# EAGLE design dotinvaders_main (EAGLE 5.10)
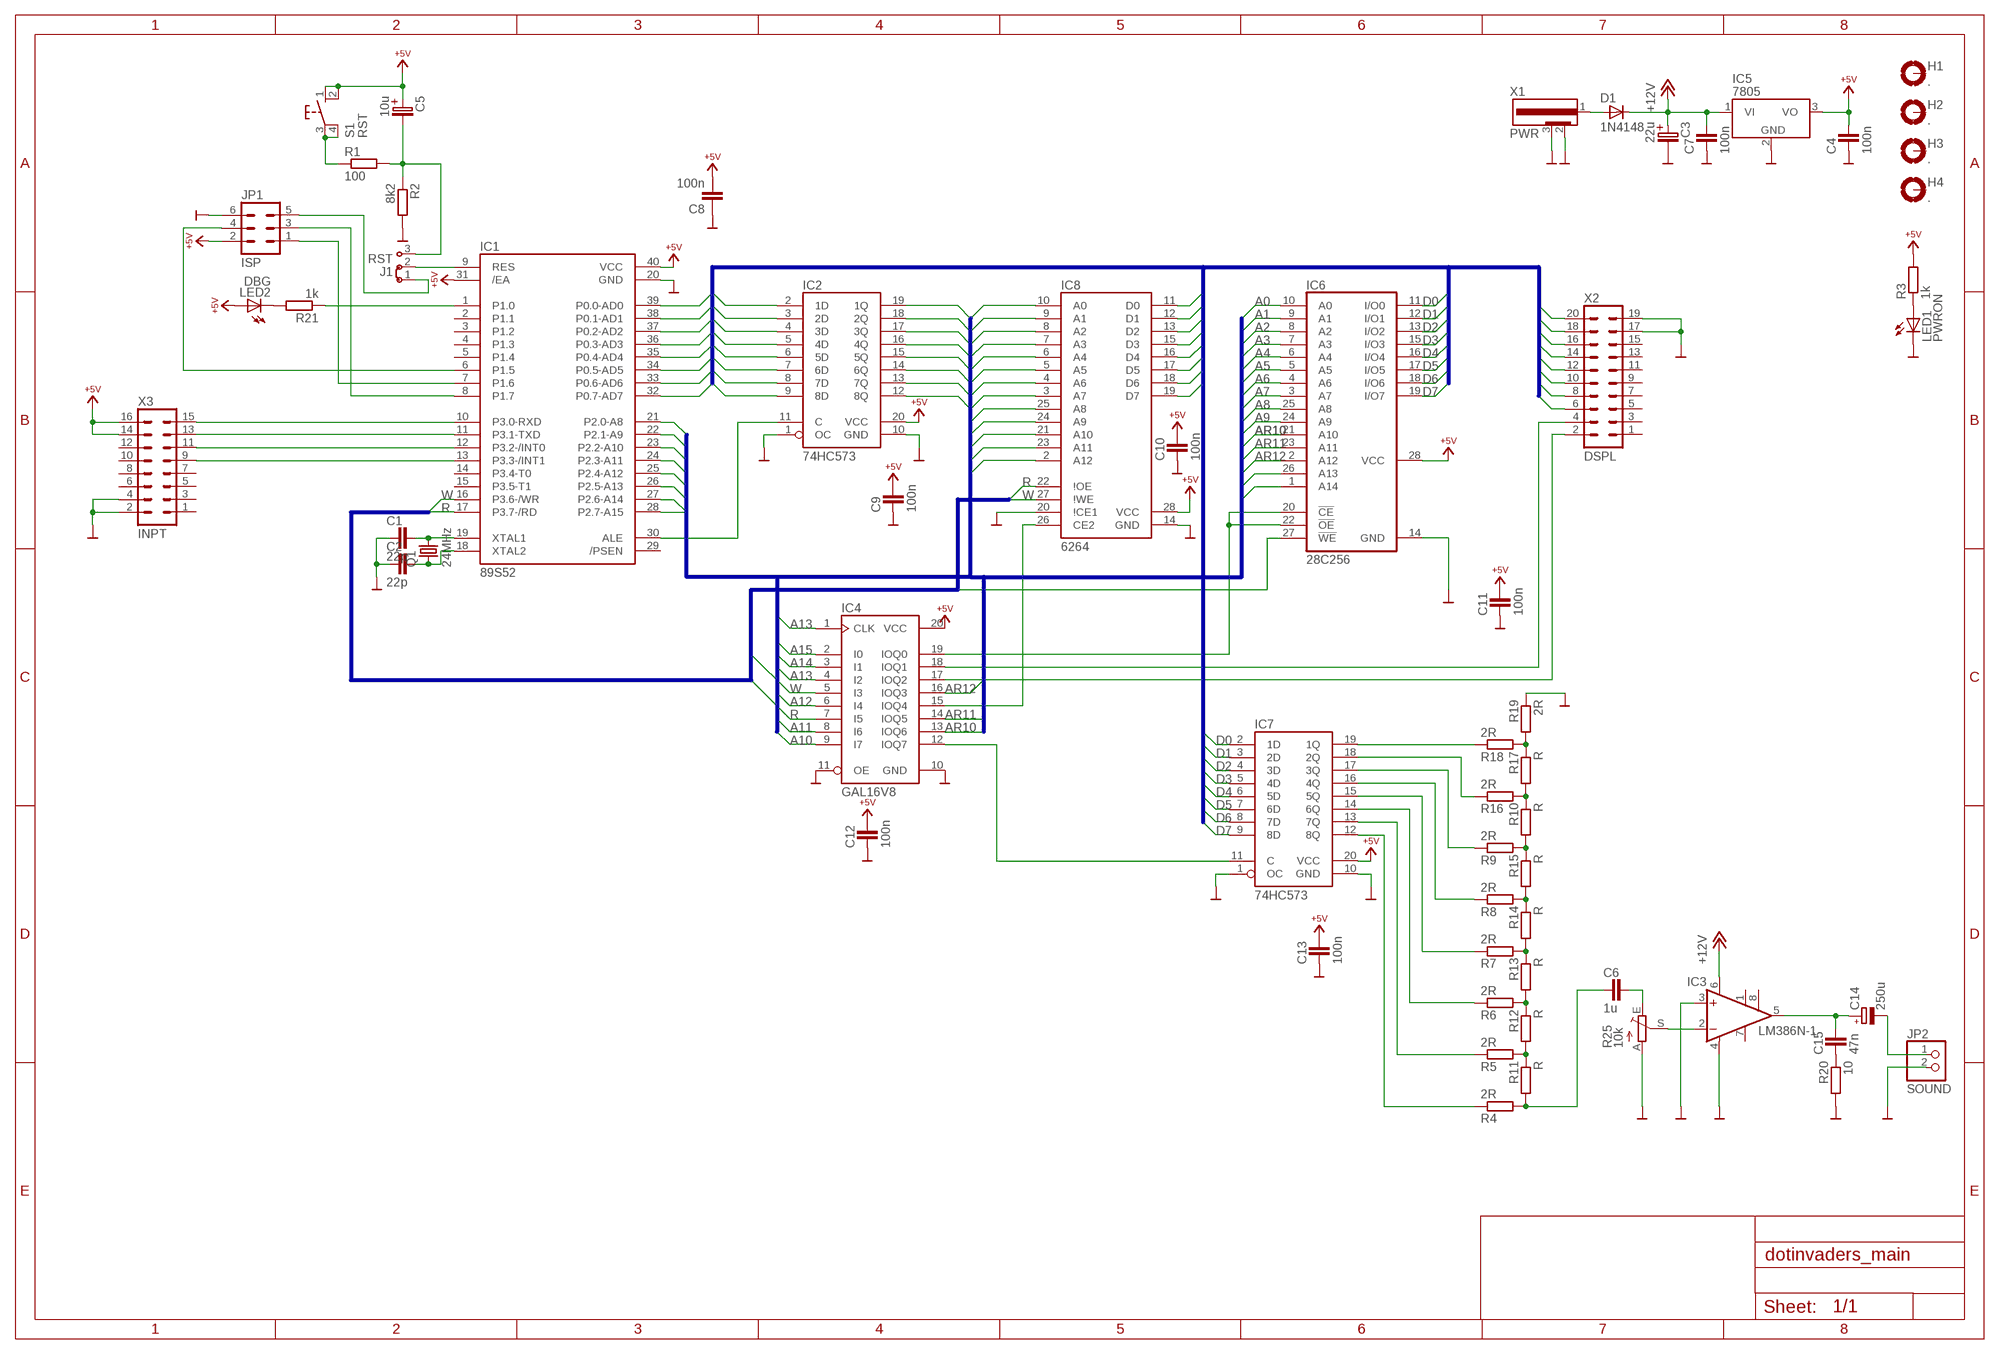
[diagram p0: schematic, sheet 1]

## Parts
C1  22p  C2,5  [C2,5]
C2  22p  C2,5  [C2,5]
C3  22u  ELKO2,5  [ELKO2,5]
C4  100n  C2,5  [C2,5]
C5  10u  ELKO2,5  [ELKO2,5]
C6  1u  C-2,5  [C-2,5]
C7  100n  C2,5  [C2,5]
C8  100n  C-EU050-024X044  [C050-024X044]
C9  100n  C-2,5  [C-2,5]
C10  100n  C-2,5  [C-2,5]
C11  100n  C-2,5  [C-2,5]
C12  100n  C-2,5  [C-2,5]
C13  100n  C-2,5  [C-2,5]
C14  250u  CPOL-EUE5-10.5  [E5-10,5]
C15  47n  C-2,5  [C-2,5]
D1  1N4148  1N4007  [DO41]
H1  .  BO3,0  [BO3,0]
H2  .  BO3,0  [BO3,0]
H3  .  BO3,0  [BO3,0]
H4  .  BO3,0  [BO3,0]
IC1  89S52  80C32  [DIL40]
IC2  74HC573  74573  [DIL20]
IC3  LM386N-1  [DIL08]
IC4  GAL16V8  16V8  [DIL20]
IC5  7805  [TO220]
IC6  28C256  [DIL28]
IC7  74HC573  74573  [DIL20]
IC8  6264  [DIL28]
J1  RST  J2X2MM  [04C]
JP1  ISP  MA3X2  [MA3X2]
JP2  SOUND  PINHD-1X2  [1X02]
LED1  PWRON  LED5MM  [LED5MM]
LED2  DBG  LED5MM  [LED5MM]
Q1  24MHz  Q  [HC49U-S]
R1  100  R-EU_R0805  [R0805]
R2  8k2  R-EU_R0805  [R0805]
R3  1k  R-EU_R0805  [R0805]
R4  2R  R-EU_R0805  [R0805]
R5  2R  R-EU_R0805  [R0805]
R6  2R  R-EU_R0805  [R0805]
R7  2R  R-EU_R0805  [R0805]
R8  2R  R-EU_R0805  [R0805]
R9  2R  R-EU_R0805  [R0805]
R10  R  R-EU_R0805  [R0805]
R11  R  R-EU_R0805  [R0805]
R12  R  R-EU_R0805  [R0805]
R13  R  R-EU_R0805  [R0805]
R14  R  R-EU_R0805  [R0805]
R15  R  R-EU_R0805  [R0805]
R16  2R  R-EU_M0805  [M0805]
R17  R  R-EU_R0805  [R0805]
R18  2R  R-EU_R0805  [R0805]
R19  2R  R-EU_R0805  [R0805]
R20  10  R-EU_0204/2V  [0204V]
R21  1k  R-EU_0204/5  [0204/5]
R25  10k  TRIM_EU-S64Y  [S64Y]
S1  RST  KEY3305  [KEY3305]
X1  PWR  DC-CON  [DC-CON]
X2  DSPL  MA10X2  [MA10X2]
X3  INPT  MA8X2  [MA8X2]

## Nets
+5V: C4.2 C5.+ C8.2 C9.2 C10.2 C11.2 C12.2 C13.2 IC1.31(/EA) IC1.40(VCC) IC2.20(VCC) IC4.20(VCC) IC5.3(VO) IC6.28(VCC) IC7.20(VCC) IC8.28(VCC) JP1.2 LED2.A R3.2 S1.1 S1.2 X3.14 X3.16
+12V: C3.+ C7.2 D1.C IC3.6(VS) IC5.1(VI)
A0: IC2.19(1Q) IC6.10(A0) IC8.10(A0)
A1: IC2.18(2Q) IC6.9(A1) IC8.9(A1)
A2: IC2.17(3Q) IC6.8(A2) IC8.8(A2)
A3: IC2.16(4Q) IC6.7(A3) IC8.7(A3)
A4: IC2.15(5Q) IC6.6(A4) IC8.6(A4)
A5: IC2.14(6Q) IC6.5(A5) IC8.5(A5)
A6: IC2.13(7Q) IC6.4(A6) IC8.4(A6)
A7: IC2.12(8Q) IC6.3(A7) IC8.3(A7)
A8: IC1.21(P2.0-A8) IC6.25(A8) IC8.25(A8)
A9: IC1.22(P2.1-A9) IC6.24(A9) IC8.24(A9)
A10: IC1.23(P2.2-A10) IC4.9(I7)
A11: IC1.24(P2.3-A11) IC4.8(I6)
A12: IC1.25(P2.4-A12) IC4.6(I4)
A13: IC1.26(P2.5-A13) IC4.1(CLK) IC4.4(I2) IC6.26(A13)
A14: IC1.27(P2.6-A14) IC4.3(I1) IC6.1(A14)
A15: IC1.28(P2.7-A15) IC4.2(I0)
AR10: IC4.13(IOQ6) IC6.21(A10) IC8.21(A10)
AR11: IC4.14(IOQ5) IC6.23(A11) IC8.23(A11)
AR12: IC4.16(IOQ3) IC6.2(A12) IC8.2(A12)
D0: IC1.39(P0.0-AD0) IC2.2(1D) IC6.11(I/O0) IC7.2(1D) IC8.11(D0) X2.20
D1: IC1.38(P0.1-AD1) IC2.3(2D) IC6.12(I/O1) IC7.3(2D) IC8.12(D1) X2.18
D2: IC1.37(P0.2-AD2) IC2.4(3D) IC6.13(I/O2) IC7.4(3D) IC8.13(D2) X2.16
D3: IC1.36(P0.3-AD3) IC2.5(4D) IC6.15(I/O3) IC7.5(4D) IC8.15(D3) X2.14
D4: IC1.35(P0.4-AD4) IC2.6(5D) IC6.16(I/O4) IC7.6(5D) IC8.16(D4) X2.12
D5: IC1.34(P0.5-AD5) IC2.7(6D) IC6.17(I/O5) IC7.7(6D) IC8.17(D5) X2.10
D6: IC1.33(P0.6-AD6) IC2.8(7D) IC6.18(I/O6) IC7.8(7D) IC8.18(D6) X2.8
D7: IC1.32(P0.7-AD7) IC2.9(8D) IC6.19(I/O7) IC7.9(8D) IC8.19(D7) X2.6
GND: C1.1 C2.1 C3.- C4.1 C7.1 C8.1 C9.1 C10.1 C11.1 C12.1 C13.1 IC1.20(GND) IC2.1(OC) IC2.10(GND) IC3.3(+IN) IC3.4(GND) IC4.10(GND) IC4.11(OE) IC5.2(GND) IC6.14(GND) IC7.1(OC) IC7.10(GND) IC8.14(GND) IC8.20(\!CE1) JP1.6 JP2.2 LED1.K(C) R2.2 R19.1 R20.2 R25.A X1.2 X1.3 X2.17 X2.19 X3.2 X3.4
N$1: IC1.30(ALE) IC2.11(C)
N$2: D1.A X1.1
N$3: C1.2 IC1.19(XTAL1) Q1.2
N$4: C2.2 IC1.18(XTAL2) Q1.1
N$5: C6.2 R25.E
N$6: IC4.12(IOQ7) IC7.11(C)
N$7: C6.1 R4.2 R11.2
N$8: LED1.A R3.1
N$9: IC4.19(IOQ0) IC6.20(!CE) IC6.22(!OE)
N$10: C5.- J1.3 R1.2 R2.1
N$11: R1.1 S1.3 S1.4
N$12: J1.1 JP1.5
N$13: IC1.8(P1.7) JP1.3
N$14: IC1.7(P1.6) JP1.1
N$15: IC1.6(P1.5) JP1.4
N$16: IC1.9(RES) J1.2
N$17: IC4.15(IOQ4) IC8.26(CE2)
N$18: IC7.18(2Q) R16.1
N$19: IC4.18(IOQ1) X2.4
N$20: IC4.17(IOQ2) X2.2
N$21: IC7.17(3Q) R9.1
N$22: IC7.16(4Q) R8.1
N$23: IC7.15(5Q) R7.1
N$24: IC7.14(6Q) R6.1
N$25: IC3.2(-IN) R25.S
N$26: R5.2 R11.1 R12.2
N$27: R6.2 R12.1 R13.2
N$28: R7.2 R13.1 R14.2
N$29: R8.2 R14.1 R15.2
N$30: R9.2 R10.2 R15.1
N$31: IC1.10(P3.0-RXD) X3.15
N$32: IC1.11(P3.1-TXD) X3.13
N$33: IC1.12(P3.2-/INT0) X3.11
N$34: IC1.13(P3.3-/INT1) X3.9
N$35: R10.1 R16.2 R17.2
N$36: R17.1 R18.2 R19.2
N$37: IC7.13(7Q) R5.1
N$38: IC7.12(8Q) R4.1
N$39: C14.+ C15.2 IC3.5(OUT)
N$40: C15.1 R20.1
N$41: C14.- JP2.1
N$42: IC7.19(1Q) R18.1
N$44: LED2.K(C) R21.2
N$45: IC1.1(P1.0) R21.1
R: IC1.17(P3.7-/RD) IC4.7(I5) IC8.22(\!OE)
W: IC1.16(P3.6-/WR) IC4.5(I3) IC6.27(!WE) IC8.27(\!WE)
Unconnected: H1.B3,0(MOUNT) H2.B3,0(MOUNT) H3.B3,0(MOUNT) H4.B3,0(MOUNT) IC1.2(P1.1) IC1.3(P1.2) IC1.4(P1.3) IC1.5(P1.4) IC1.14(P3.4-T0) IC1.15(P3.5-T1) IC1.29(/PSEN) IC3.1(GAIN) IC3.7(BYPASS) IC3.8(GAIN) X2.1 X2.3 X2.5 X2.7 X2.9 X2.11 X2.13 X2.15 X3.1 X3.3 X3.5 X3.6 X3.7 X3.8 X3.10 X3.12

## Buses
AD:A[0..15],AR[8..15]
D[0..7]
RW:R,W

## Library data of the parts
C1 C2 C4 C7 = 8032mini:C2,5
C3 C5 = 8032mini:ELKO2,5
C6 C9-C13 C15 = 89S52mini2:C-2,5
C8 = rcl:C-EU: CAPACITOR, European symbol
C14 = rcl:CPOL-EU: POLARIZED CAPACITOR, European symbol
D1 = 8032mini:1N4007
H1-H4 = 8032mini:BO3,0
IC1 = 8032mini:80C32
IC2 IC7 = 8032mini:74573
IC3 = dotinvaders:LM386?-*: Low Voltage Audio Power Amplifier Source: http://cache.national.com/ds/LM/LM386.pdf
IC4 = 8032mini:16V8
IC5 = 8032mini:7805
IC6 = dotinvaders:28C256
IC8 = 89S52mini2:6264
J1 = jumper:J2: Jumper switch 2 x 2.5 mm
JP1 = 89S52mini2:MA3X2
JP2 = pinhead:PINHD-1X2: PIN HEADER
LED1 LED2 = led:LED: LED
Q1 = 8032mini:Q
R1-R21 = rcl:R-EU_: RESISTOR, European symbol
R25 = pot:TRIM_EU-: POTENTIOMETER
S1 = 8032mini:KEY3305
X1 = 8032mini:DC-CON
X2 = 89S52mini2:MA10X2
X3 = 89S52mini2:MA8X2

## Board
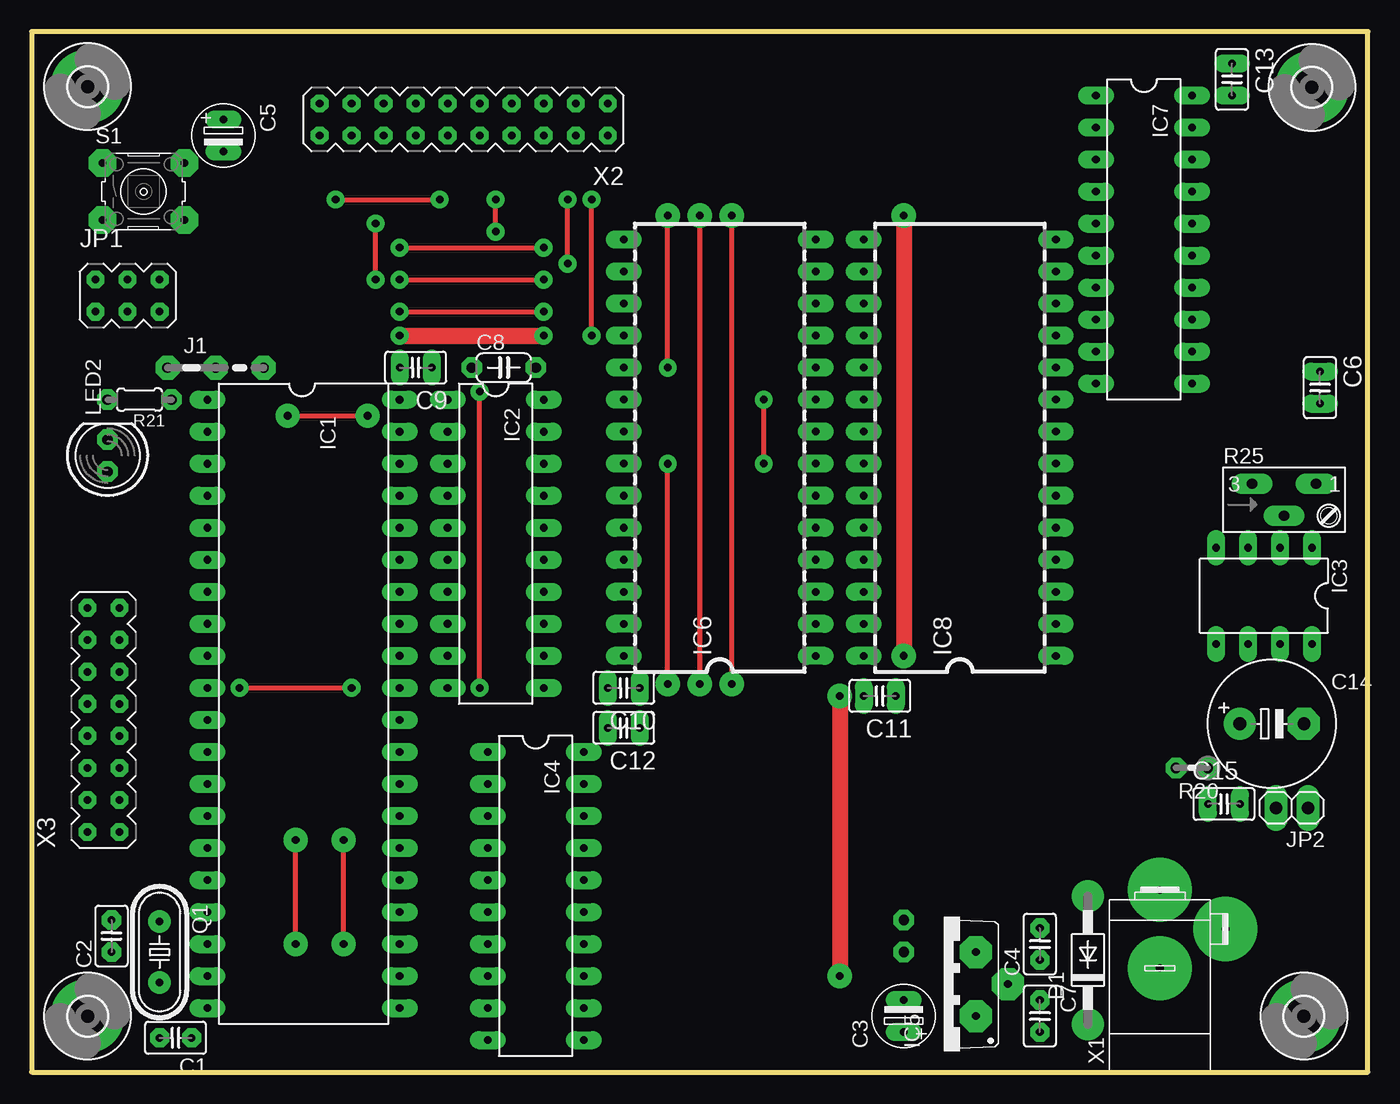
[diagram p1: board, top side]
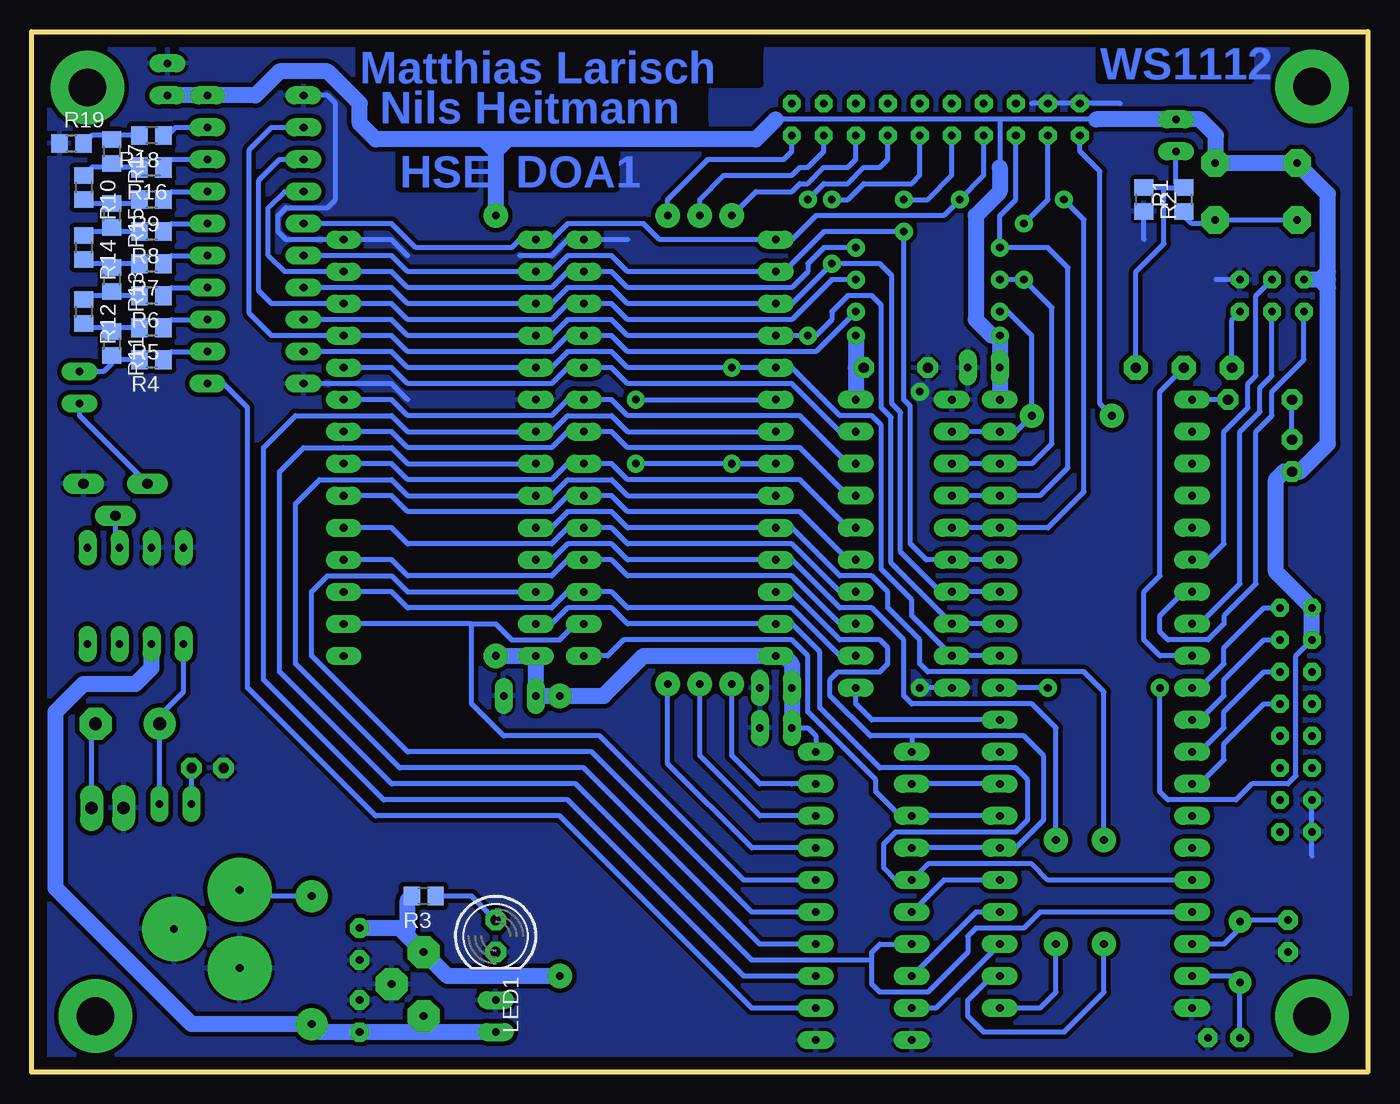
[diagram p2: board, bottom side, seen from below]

Size 106.04 x 82.54 mm. Coordinates in mm from the lower left corner, seen from the top.
Outline: 0,0 106.04,0 106.04,82.54 0,82.54 0,0
Copper layers (1*16): Top 0.035mm / dielectric 1.5mm / Bottom 0.035mm
Design rules "default *": minimum track width 16mil, minimum drill 10mil, track to track 14mil, track to pad 14mil, pad to pad 14mil, via to via 14mil, smd to smd 8mil, copper to edge 40mil, drill to drill 8mil, minimum pad ring 16mil, minimum via ring 16mil, stop-mask expansion 4mil, vias tented up to drill 0mil, thermal gap 10mil

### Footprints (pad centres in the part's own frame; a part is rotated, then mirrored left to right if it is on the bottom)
C2,5 = drill 0.61 pad 1.524 octagon: 1 -1.27,0; 2 1.27,0
ELKO2,5 = drill 0.61 pad 1.422 long: + -1.27,0; - 1.27,0
C-2,5 = drill 0.6 pad 1.422 long: 1 -1.27,0; 2 1.27,0
C050-024X044 = drill 0.813 octagon: 1 -2.54,0; 2 2.54,0
E5-10,5 = drill 1.016 pad 2.54 round: + -2.54,0 | drill 1.016 pad 2.54 octagon: - 2.54,0
DO41 = drill 0.61 pad 2.54 round: A 5.08,0; C -5.08,0
BO3,0 = drill 3 pad 5.842 round: B3,0 0,0
DIL40 = drill 0.61 pad 1.422 long: 1 -24.13,-7.62; 2 -21.59,-7.62; 3 -19.05,-7.62; 4 -16.51,-7.62; 5 -13.97,-7.62; 6 -11.43,-7.62; 7 -8.89,-7.62; 8 -6.35,-7.62; 9 -3.81,-7.62; 10 -1.27,-7.62; 11 1.27,-7.62; 12 3.81,-7.62; 13 6.35,-7.62; 14 8.89,-7.62; 15 11.43,-7.62; 16 13.97,-7.62; 17 16.51,-7.62; 18 19.05,-7.62; 19 21.59,-7.62; 20 24.13,-7.62; 21 24.13,7.62; 22 21.59,7.62; 23 19.05,7.62; 24 16.51,7.62; 25 13.97,7.62; 26 11.43,7.62; 27 8.89,7.62; 28 6.35,7.62; 29 3.81,7.62; 30 1.27,7.62; 31 -1.27,7.62; 32 -3.81,7.62; 33 -6.35,7.62; 34 -8.89,7.62; 35 -11.43,7.62; 36 -13.97,7.62; 37 -16.51,7.62; 38 -19.05,7.62; 39 -21.59,7.62; 40 -24.13,7.62
DIL20 = drill 0.61 pad 1.422 long: 1 -11.43,-3.81; 2 -8.89,-3.81; 3 -6.35,-3.81; 4 -3.81,-3.81; 5 -1.27,-3.81; 6 1.27,-3.81; 7 3.81,-3.81; 8 6.35,-3.81; 9 8.89,-3.81; 10 11.43,-3.81; 11 11.43,3.81; 12 8.89,3.81; 13 6.35,3.81; 14 3.81,3.81; 15 1.27,3.81; 16 -1.27,3.81; 17 -3.81,3.81; 18 -6.35,3.81; 19 -8.89,3.81; 20 -11.43,3.81
DIL08 = drill 0.6 pad 1.422 long: 1 -3.81,-3.81; 2 -1.27,-3.81; 3 1.27,-3.81; 4 3.81,-3.81; 5 3.81,3.81; 6 1.27,3.81; 7 -1.27,3.81; 8 -3.81,3.81
TO220 = drill 0.61 pad 2.54 octagon: 1 -2.54,0; 2 0,-2.54; 3 2.54,0
DIL28 = drill 0.6 pad 1.422 long: 1 -16.51,-7.62; 2 -13.97,-7.62; 3 -11.43,-7.62; 4 -8.89,-7.62; 5 -6.35,-7.62; 6 -3.81,-7.62; 7 -1.27,-7.62; 8 1.27,-7.62; 9 3.81,-7.62; 10 6.35,-7.62; 11 8.89,-7.62; 12 11.43,-7.62; 13 13.97,-7.62; 14 16.51,-7.62; 15 16.51,7.62; 16 13.97,7.62; 17 11.43,7.62; 18 8.89,7.62; 19 6.35,7.62; 20 3.81,7.62; 21 1.27,7.62; 22 -1.27,7.62; 23 -3.81,7.62; 24 -6.35,7.62; 25 -8.89,7.62; 26 -11.43,7.62; 27 -13.97,7.62; 28 -16.51,7.62
04C = drill 0.813 pad 1.905 octagon: 1 -1.905,0; 2 1.905,0; 3 5.715,0
MA3X2 = drill 0.6 pad 1.27 octagon: 1 -2.54,-1.27; 2 -2.54,1.27; 3 0,-1.27; 4 0,1.27; 5 2.54,-1.27; 6 2.54,1.27
1X02 = drill 1.016 long: 1 -1.27,0; 2 1.27,0
LED5MM = drill 0.813 octagon: A -1.27,0; K 1.27,0
HC49U-S = drill 0.61 pad 1.778 round: 1 -2.413,0; 2 2.413,0
R0805 = smd 1.3 x 1.5: 1 -0.95,0; 2 0.95,0
M0805 = smd 1.3 x 1.6: 1 -0.95,0; 2 0.95,0
0204V = drill 0.813 octagon: 1 -1.27,0; 2 1.27,0
0204/5 = drill 0.813 octagon: 1 -2.54,0; 2 2.54,0
S64Y = drill 0.813 long: A 2.54,1.27; E -2.54,1.27; S 0,-1.27
KEY3305 = drill 0.61 pad 2.184 octagon: 1 -3.251,2.261; 2 3.251,2.261; 3 -3.251,-2.261; 4 3.251,-2.261
DC-CON = drill 0.61 pad 5.08 round: 1 6.2,0; 2 3.1,-5.2; 3 0,0
MA10X2 = drill 0.6 pad 1.27 octagon: 1 -11.43,-1.27; 2 -11.43,1.27; 3 -8.89,-1.27; 4 -8.89,1.27; 5 -6.35,-1.27; 6 -6.35,1.27; 7 -3.81,-1.27; 8 -3.81,1.27; 9 -1.27,-1.27; 10 -1.27,1.27; 11 1.27,-1.27; 12 1.27,1.27; 13 3.81,-1.27; 14 3.81,1.27; 15 6.35,-1.27; 16 6.35,1.27; 17 8.89,-1.27; 18 8.89,1.27; 19 11.43,-1.27; 20 11.43,1.27
MA8X2 = drill 0.6 pad 1.27 octagon: 1 -8.89,-1.27; 2 -8.89,1.27; 3 -6.35,-1.27; 4 -6.35,1.27; 5 -3.81,-1.27; 6 -3.81,1.27; 7 -1.27,-1.27; 8 -1.27,1.27; 9 1.27,-1.27; 10 1.27,1.27; 11 3.81,-1.27; 12 3.81,1.27; 13 6.35,-1.27; 14 6.35,1.27; 15 8.89,-1.27; 16 8.89,1.27

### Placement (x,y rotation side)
C1  11.43,2.72 180 top
C2  6.35,10.79 90 top
C3  69.22,4.45 90 top
C4  80.01,10.16 90 top
C5  15.24,74.3 270 top
C6  102.24,54.29 270 top
C7  80.01,4.45 270 top
C8  37.47,55.88 0 top
C9  30.48,55.88 180 top
C10  46.99,30.48 180 top
C11  67.31,29.84 180 top
C12  46.99,27.3 180 top
C13  95.25,78.74 270 top
C14  98.43,27.62 0 top
C15  94.62,21.27 0 top
D1  83.82,8.89 90 top
H1  100.97,4.45 0 top
H2  101.6,78.1 0 top
H3  4.45,78.17 0 top
H4  4.45,4.45 0 top
IC1  21.59,29.21 270 top
IC2  36.83,41.91 270 top
IC3  97.79,37.78 180 top
IC4  40.01,13.97 270 top
IC5  74.93,6.98 90 top
IC6  54.61,49.53 90 top
IC7  88.26,66.04 270 top
IC8  73.66,49.53 90 top
J1  12.7,55.88 0 top
JP1  7.62,61.6 0 top
JP2  100.01,20.95 180 top
LED1  69.22,10.79 270 bottom
LED2  6.03,48.9 90 top
Q1  10.16,9.53 270 top
R1  14.61,69.21 90 bottom
R2  17.78,69.21 270 bottom
R3  74.93,13.97 180 bottom
R4  96.52,56.52 180 bottom
R5  96.52,59.05 180 bottom
R6  96.52,61.6 180 bottom
R7  96.52,64.14 180 bottom
R8  96.52,66.67 180 bottom
R9  96.52,69.21 180 bottom
R10  101.92,70.17 270 bottom
R11  99.69,57.79 270 bottom
R12  101.92,60.33 270 bottom
R13  99.69,62.87 270 bottom
R14  101.92,65.41 270 bottom
R15  99.69,67.94 270 bottom
R16  96.52,71.75 180 bottom
R17  99.69,73.02 270 bottom
R18  96.52,74.3 180 bottom
R19  102.87,73.66 0 bottom
R20  92.07,24.13 180 top
R21  8.57,53.34 180 top
R25  99.38,45.4 0 top
S1  8.89,69.85 0 top
X1  89.53,8.26 90 top
X2  34.29,75.56 180 top
X3  5.71,27.94 90 top

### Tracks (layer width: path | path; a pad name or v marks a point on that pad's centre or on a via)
+5V  (via drill 0.6, 0.6 pad 1.93, 0.61, 0.61 pad 1.93)
  Top 0.406: v16.51,30.48 v25.4,30.48
  Top 1.27: v29.21,58.42 v40.64,58.42 | v69.22,67.94 v69.22,33.02 | v64.13,29.84 v64.13,7.62
  Bottom 0.406: 12.42,72.39 S1.2 12.07,72.19 | 76.2,11.43 76.84,11.43 | IC4.20 43.81,26.67 44.45,27.3 C12.2 | 3.18,62.87 3.81,62.87 | IC6.28 46.35,33.02 | v25.4,30.48 IC1.31 | v16.51,30.48 16.51,22.22 15.88,21.59 10.48,21.59 9.21,22.86 6.35,22.86 5.71,23.5 5.71,33.02 X3.14 | LED2.A 6.35,47.62 | 21.59,75.56 29.21,75.56 | 29.21,75.56 46.99,75.56 | 29.21,75.56 29.21,71.75
  Bottom 1.27: v40.64,58.42 40.64,55.88 | 40.64,55.88 IC2.20 | X3.14 X3.16 7.3,39.69 7.3,46.99 6.67,47.62 LED2.A 5.4,47.62 3.18,49.85 3.18,62.23 | S1.2 S1.1 3.18,69.65 3.18,63.5 | 76.2,10.79 IC5.3 73.03,7.62 v64.13,7.62 | 76.2,10.79 76.2,11.43 76.2,13.65 R3.2 | C4.2 76.84,11.43 76.2,10.79 | v69.22,33.02 IC8.28 C11.2 v64.13,29.84 60.64,29.84 57.47,33.02 IC6.28 | 69.22,73.98 69.22,73.02 | 69.22,73.02 v69.22,67.94 | C12.2 C10.2 45.72,32.38 46.35,33.02 | C13.2 IC7.20 88.26,77.47 86.36,79.38 82.55,79.38 80.01,76.83 80.01,75.25 78.74,73.98 70.17,73.98 | 12.07,72.19 12.07,74.3 13.34,75.56 C5.+ 21.59,75.56 | 40.64,55.88 C8.2 | 68.26,73.98 69.22,73.98 | 3.18,62.23 3.18,62.87 3.18,63.5 | 3.81,62.87 JP1.2 | IC1.40 C9.2 v29.21,58.42 29.84,58.42 31.12,59.69 31.12,67.94 29.21,69.85 29.21,71.75 | 69.22,73.02 70.17,73.98 | 69.22,73.98 70.17,73.98 | 68.26,73.98 69.22,73.02 | 3.18,62.23 3.81,62.87 | 3.81,62.87 3.18,63.5 | 68.26,73.98 48.58,73.98 46.99,75.56
+12V
  Bottom 0.406: 74.93,3.17 IC5.1
  Bottom 1.27: C3.+ 74.93,3.17 C7.2 83.19,3.17 D1.C 93.34,3.81 104.14,14.61 104.14,28.57 101.92,30.8 97.79,30.8 96.52,32.07 IC3.6
A0
  Bottom 0.406: IC2.19 41.91,50.8 45.72,54.61 58.74,54.61 60.01,55.88 IC6.10 63.5,55.88 64.77,54.61 76.2,54.61 77.47,55.88 IC8.10
A1
  Bottom 0.406: IC2.18 41.27,48.26 45.09,52.07 58.74,52.07 60.01,53.34 IC6.9 | IC8.9 77.47,53.34 76.2,52.07 64.77,52.07 63.5,53.34 IC6.9 | IC6.9 62.87,53.34
A2
  Bottom 0.406: IC2.17 41.27,45.72 45.09,49.53 58.74,49.53 60.01,50.8 IC6.8 63.5,50.8 64.77,49.53 76.2,49.53 77.47,50.8 IC8.8
A3
  Bottom 0.406: IC2.16 41.27,43.18 45.09,46.99 58.74,46.99 60.01,48.26 IC6.7 63.5,48.26 64.77,46.99 76.2,46.99 77.47,48.26 IC8.7
A4
  Bottom 0.406: IC2.15 41.27,40.64 45.09,44.45 58.74,44.45 60.01,45.72 IC6.6 63.5,45.72 64.77,44.45 76.2,44.45 77.47,45.72 IC8.6
A5
  Bottom 0.406: IC2.14 41.91,38.1 45.72,41.91 58.74,41.91 60.01,43.18 IC6.5 63.5,43.18 64.77,41.91 76.2,41.91 77.47,43.18 IC8.5
A6
  Bottom 0.406: IC8.4 77.47,40.64 76.2,39.37 64.77,39.37 63.5,40.64 IC6.4 60.01,40.64 58.74,39.37 45.72,39.37 41.91,35.56 IC2.13
A7
  Bottom 0.406: IC8.3 77.47,38.1 76.2,36.83 64.77,36.83 63.5,38.1 IC6.3 60.01,38.1 58.74,36.83 45.72,36.83 41.91,33.02 IC2.12
A8  (via drill 0.61 pad 1.93)
  Top 0.406: v24.77,10.16 v24.77,18.41
  Bottom 0.406: IC8.25 64.77,40.64 63.5,41.91 60.01,41.91 58.74,40.64 IC6.25 45.72,40.64 41.91,36.83 39.37,36.83 36.83,34.29 36.83,29.84 36.2,29.21 26.67,29.21 24.77,27.3 v24.77,18.41 | IC1.21 26.04,5.08 24.77,6.35 v24.77,10.16
A9  (via drill 0.61 pad 1.93)
  Top 0.406: v20.96,10.16 v20.96,18.41
  Bottom 0.406: IC8.24 64.77,43.18 63.5,44.45 60.01,44.45 58.74,43.18 IC6.24 45.72,43.18 41.91,39.37 39.37,39.37 38.1,38.1 38.1,36.83 35.56,34.29 35.56,32.38 34.92,31.75 22.54,31.75 20.96,30.16 v20.96,18.41 | IC1.22 29.84,7.62 31.75,5.71 31.75,4.45 30.48,3.17 24.13,3.17 20.96,6.35 v20.96,10.16
A10
  Bottom 0.406: IC4.9 34.29,5.08 IC1.23
A11
  Bottom 0.406: IC1.24 31.12,12.7 IC4.8
A12
  Bottom 0.406: IC1.25 33.66,15.24 IC4.6
A13
  Bottom 0.406: 36.2,26.67 27.3,26.67 25.72,25.08 25.72,20 27.94,17.78 IC1.26 IC4.4 | 36.2,26.67 39.5,26.67 42.67,29.84 42.67,31.11 42.04,31.75 38.73,31.75 38.1,32.38 38.1,33.66 38.73,34.29 41.91,34.29 45.72,38.1 IC6.26 | 36.2,26.67 IC4.1
A14
  Bottom 0.406: IC1.27 IC4.3 37.15,20.32 39.05,22.22 39.05,23.18 44.45,28.57 44.45,33.02 45.72,34.29 59.05,34.29 60.33,33.02 IC6.1
A15
  Bottom 0.406: IC1.28 IC4.2
AR10
  Bottom 0.406: IC4.13 49.53,7.62 63.5,21.59 78.1,21.59 87.63,31.11 87.63,49.53 85.09,52.07 77.47,52.07 76.2,50.8 IC8.21 64.77,50.8 63.5,52.07 60.01,52.07 58.74,50.8 IC6.21
AR11
  Bottom 0.406: IC4.14 48.26,10.16 62.23,24.13 76.84,24.13 85.09,32.38 85.09,45.09 83.19,46.99 77.47,46.99 76.2,45.72 IC8.23 64.77,45.72 63.5,46.99 60.01,46.99 58.74,45.72 IC6.23
AR12
  Bottom 0.406: 71.12,35.56 69.22,35.56 67.94,34.29 64.13,34.29 62.87,35.56 IC6.2 | 71.12,35.56 IC8.2 | IC4.16 49.53,15.24 60.96,26.67 68.58,26.67 71.12,29.21 71.12,35.56
D0  (via drill 0.61, 0.61 pad 1.93)
  Top 0.406: v29.21,60.33 v40.64,60.33 | v20.32,52.07 v26.67,52.07
  Bottom 0.406: IC2.2 IC1.39 27.94,50.8 v26.67,52.07 26.67,58.42 28.57,60.33 v29.21,60.33 | IC7.2 87,74.93 88.77,73.15 88.77,60.2 87,58.42 IC8.11 77.47,58.42 76.2,57.15 64.77,57.15 63.5,58.42 IC6.11 60.01,58.42 58.74,57.15 43.81,57.15 v40.64,60.33 | X2.20 22.86,73.02 21.27,71.44 21.27,53.02 v20.32,52.07
D1  (via drill 0.61)
  Top 0.406: v29.21,62.87 v40.64,62.87 | v27.3,62.87 v27.3,67.31
  Bottom 0.406: IC2.3 IC1.38 26.67,48.26 25.08,49.85 25.08,60.64 v27.3,62.87 v29.21,62.87 | IC7.3 86.36,72.39 88.01,70.74 88.01,61.98 87,60.96 IC8.12 77.47,60.96 76.2,59.69 64.77,59.69 63.5,60.96 IC6.12 60.01,60.96 58.74,59.69 45.72,59.69 42.55,62.87 v40.64,62.87 | X2.18 25.4,69.21 v27.3,67.31
D2  (via drill 0.61)
  Top 0.406: v29.21,65.41 v40.64,65.41
  Bottom 0.406: IC2.4 IC1.37 26.04,45.72 23.81,47.94 23.81,63.82 25.4,65.41 v29.21,65.41 29.21,67.94 27.94,69.21 X2.16 | v40.64,65.41 43.18,65.41 44.45,64.14 44.45,63.5 45.72,62.23 58.74,62.23 60.01,63.5 IC6.13 63.5,63.5 64.77,62.23 76.2,62.23 77.47,63.5 IC8.13 85.98,63.5 87.25,64.77 87.25,68.58 85.98,69.85 IC7.4
D3  (via drill 0.6)
  Top 0.406: v24.13,69.21 v32.39,69.21
  Bottom 0.406: IC2.5 IC1.36 25.4,43.18 22.54,46.04 22.54,67.63 v24.13,69.21 | IC7.5 77.47,67.31 76.2,66.04 75.56,65.41 67.94,65.41 67.31,66.04 IC8.15 64.77,66.04 63.5,67.31 57.47,67.31 56.2,66.04 IC6.15 45.72,66.04 43.81,67.94 33.66,67.94 v32.39,69.21 30.48,71.12 X2.14
D4  (via drill 0.61)
  Top 0.406: v36.83,66.67 v36.83,69.21
  Bottom 0.406: IC1.35 IC2.6 35.05,40.64 36.32,41.91 36.32,52.83 36.83,53.34 v36.83,66.67 43.18,66.67 46.35,63.5 IC6.16 58.74,63.5 60.01,64.77 63.5,64.77 64.77,63.5 IC8.16 76.2,63.5 77.47,64.77 IC7.6 | X2.12 33.02,71.12 34.92,69.21 v36.83,69.21
D5  (via drill 0.61)
  Top 0.406: v42.55,64.14 v42.55,69.21
  Bottom 0.406: IC1.34 IC2.7 33.91,38.1 37.08,41.28 37.08,52.32 37.78,53.02 37.78,63.18 38.73,64.14 v42.55,64.14 45.72,60.96 IC6.17 58.74,60.96 60.01,62.23 63.5,62.23 64.77,60.96 IC8.17 76.2,60.96 77.47,62.23 IC7.7 | X2.10 35.56,71.12 36.2,70.48 40.01,70.48 41.27,69.21 v42.55,69.21
D6  (via drill 0.61)
  Top 0.406: v44.45,58.42 v44.45,69.21
  Bottom 0.406: IC1.33 IC2.8 37.85,40.39 37.85,51.94 38.61,52.71 38.61,60.83 39.37,61.6 41.27,61.6 42.55,60.33 42.55,59.69 43.81,58.42 v44.45,58.42 IC6.18 58.74,58.42 60.01,59.69 63.5,59.69 64.77,58.42 IC8.18 76.2,58.42 77.47,59.69 IC7.8 | X2.8 38.1,72.39 38.73,71.75 40.01,71.75 41.27,70.48 43.18,70.48 v44.45,69.21
D7  (via drill 0.61, 0.61 pad 1.93)
  Top 0.406: v50.48,55.88 v50.48,67.94
  Bottom 0.406: IC1.32 IC2.9 36.2,36.2 36.2,37.47 38.61,39.88 38.61,51.31 39.37,52.07 41.91,52.07 45.72,55.88 IC6.19 v50.48,55.88 58.74,55.88 60.01,57.15 63.5,57.15 64.77,55.88 IC8.19 76.2,55.88 77.47,57.15 IC7.9 | v50.48,67.94 48.58,69.85 45.72,69.85 45.09,70.48 44.45,70.48 43.18,71.75 41.27,71.75 40.64,72.39 X2.6
GND  (via drill 0.6)
  Top 0.406: v35.56,30.48 v35.56,53.98
  Bottom 0.406: 76.2,53.34 77.47,54.61 IC7.10 | 76.2,64.77 77.47,66.04 IC8.14 85.85,66.04 86.49,66.67 86.49,67.94 85.85,68.58 82.55,68.58 81.91,69.21 81.91,76.83 82.55,77.47 IC7.1 | IC1.20 13.34,5.08 | X3.4 X3.2 4.45,17.14 | 19.69,76.83 X2.19 X2.17 26.67,76.83 | JP1.6 12.07,62.87 | 17.78,66.04 R2.2 | IC2.10 v35.56,30.48 | 67.31,64.77 64.77,64.77 63.5,66.04 IC6.14 58.74,66.04
  pour Bottom (isolate 0.356): 0,0 106.04,0 106.04,82.54 0,82.54
N$1
  Bottom 0.406: IC1.30 39.37,27.94 40.64,29.21 IC2.11
N$2
  Bottom 0.406: D1.A 89.05,13.97 X1.1
N$3
  Bottom 0.406: IC1.19 10.29,7.62 10.16,7.49 Q1.2 C1.2
N$4
  Bottom 0.406: IC1.18 11.43,10.16 10.16,11.43 | 10.16,11.43 Q1.1 | C2.2 9.53,12.06 10.16,11.43
N$5
  Bottom 0.406: R25.E 102.24,52.07 C6.2
N$6
  Bottom 0.406: IC4.12 48.9,5.08 64.13,20.32 78.74,20.32 88.9,30.48 88.9,52.71 90.81,54.61 IC7.11
N$7
  Bottom 0.406: R4.2 99.38,56.52 R11.2 99.69,56.2 100.33,55.56 C6.1
N$8
  Bottom 0.406: LED1.A 71.12,13.97 R3.1
N$9  (via drill 0.6, 0.61, 0.61 pad 1.93)
  Top 0.406: v50.48,30.8 v50.48,48.26 | v58.1,48.26 v58.1,53.34
  Bottom 0.406: 45.72,22.86 IC4.19 48.26,22.86 50.48,25.08 v50.48,30.8 | v50.48,48.26 IC6.22 v58.1,48.26 | v58.1,53.34 IC6.20
N$10
  Bottom 0.406: C5.- 15.24,70.48 14.92,70.16 R1.2 16.19,70.16 | J1.3 18.41,63.5 16.19,65.72 16.19,70.16 | 16.19,70.16 R2.1
N$11
  Bottom 0.406: S1.3 S1.4 | S1.4 12.14,67.23 | S1.4 12.42,67.31 13.97,67.31 14.61,67.94 R1.1
N$12
  Bottom 0.406: J1.1 10.79,59.69 JP1.5
N$13
  Bottom 0.406: IC1.8 13.34,35.56 10.16,38.74 10.16,50.8 8.57,52.39 8.57,54.29 7.62,55.25 JP1.3
N$14
  Bottom 0.406: IC1.7 14.61,38.1 16.51,36.2 16.51,34.93 15.88,34.29 12.7,34.29 11.43,35.56 11.43,36.2 8.89,38.74 8.89,50.8 7.62,52.07 7.62,53.98 5.08,56.52 JP1.1
N$15
  Bottom 0.406: 13.34,40.64 IC1.6 12.7,40.64 11.43,41.91 11.43,50.8 9.53,52.71 9.53,54.61 8.89,55.25 8.89,61.6 JP1.4
N$16
  Bottom 0.406: IC1.9 16.51,33.02 17.78,34.29 17.78,38.1 16.51,39.37 16.51,53.98 J1.2
N$17
  Bottom 0.406: IC8.26 76.2,38.1 77.47,39.37 81.28,39.37 82.55,39.37 83.82,38.1 83.82,33.02 76.2,25.4 61.59,25.4 48.9,12.7 IC4.15
N$18
  Bottom 0.406: IC7.18 94.94,72.39 R16.1
N$19  (via drill 0.61 pad 1.93)
  Top 0.406: v53.02,30.8 v53.02,67.94
  Bottom 0.406: IC4.18 48.26,20.32 53.02,25.08 v53.02,30.8 | v53.02,67.94 53.02,69.21 51.12,71.12 45.72,71.12 45.09,71.75 44.45,71.75 43.18,73.02 X2.4
N$20  (via drill 0.61 pad 1.93)
  Top 0.406: v55.56,30.8 v55.56,67.94
  Bottom 0.406: IC4.17 48.9,17.78 55.56,24.45 v55.56,30.8 | v55.56,67.94 55.56,69.21 52.39,72.39 46.35,72.39 45.72,73.02 X2.2
N$21
  Bottom 0.406: IC7.17 94.94,69.85 R9.1
N$22
  Bottom 0.406: IC7.16 94.94,67.31 R8.1
N$23
  Bottom 0.406: IC7.15 94.94,64.77 R7.1
N$24
  Bottom 0.406: IC7.14 94.94,62.23 R6.1
N$25
  Bottom 0.406: IC3.2 99.38,41.91 R25.S
N$26
  Bottom 0.406: R5.2 99.69,59.05 | 99.69,59.05 101.6,59.05 R12.2 | 99.69,59.05 R11.1
N$27
  Bottom 0.406: R6.2 100.01,61.6 | 100.01,61.6 101.6,61.6 R12.1 | R13.2 100.01,61.6
N$28
  Bottom 0.406: R7.2 99.38,64.14 | 99.38,64.14 101.6,64.14 R14.2 | R13.1 | R13.1 100.01,63.5 | 99.38,64.14 R13.1
N$29
  Bottom 0.406: R8.2 99.69,66.67 | 99.69,66.67 101.6,66.67 | 101.6,66.67 R14.1 | 101.6,66.67 101.6,66.36 101.92,66.67 | 99.69,66.67 R15.2
N$30
  Bottom 0.406: R9.2 97.79,68.89 R15.1 101.59,68.89 R10.2
N$31
  Bottom 0.406: IC1.10 13.34,30.48 11.43,32.38 11.43,33.66 8.26,36.83 X3.15
N$32
  Bottom 0.406: IC1.11 13.34,27.94 11.43,29.84 11.43,31.11 8.26,34.29 X3.13
N$33
  Bottom 0.406: IC1.12 13.34,25.4 11.43,27.3 11.43,28.57 8.26,31.75 X3.11
N$34
  Bottom 0.406: IC1.13 13.34,22.86 11.43,24.77 11.43,26.04 8.26,29.21 X3.9
N$35
  Bottom 0.406: R16.2 98.74,71.75 99.38,71.75 | 99.38,71.75 R17.2 | 99.38,71.75 101.28,71.75 R10.1
N$36
  Bottom 0.406: R18.2 98.11,74.3 99.38,74.3 | 99.38,74.3 R17.1 | 99.38,74.3 101.28,74.3 R19.2
N$37
  Bottom 0.406: IC7.13 94.94,59.69 R5.1
N$38
  Bottom 0.406: IC7.12 94.94,57.15 R4.1
N$39
  Bottom 0.406: IC3.5 93.98,30.16 95.88,28.26 C14.+ C15.2
N$40
  Bottom 0.406: C15.1 R20.1
N$41
  Bottom 0.406: C14.- 101.28,27.3 JP2.1
N$42
  Bottom 0.406: IC7.19 94.62,74.93 95.25,74.3 R18.1
N$44
  Bottom 0.406: LED2.K R21.2
N$45
  Bottom 0.406: R21.1 IC1.1
R
  Bottom 0.406: IC8.22 76.2,48.26 77.47,49.53 81.28,49.53 84.46,49.53 86.36,47.62 86.36,31.75 77.47,22.86 62.87,22.86 48.9,8.89 39.37,8.89 | 37.47,10.16 IC4.7 38.73,10.16 39.37,9.53 39.37,8.89 | IC1.17 26.04,12.7 27.3,11.43 31.12,11.43 31.75,10.79 31.75,9.53 34.92,6.35 38.73,6.35 39.37,6.98 39.37,8.89
W
  Bottom 0.406: IC1.16 25.4,15.24 26.67,16.51 34.92,16.51 IC4.5 37.47,15.24 38.42,16.19 38.42,18.1 37.47,19.05 27.94,19.05 26.99,20 26.99,23.18 27.94,24.13 38.73,24.13 43.5,28.89 43.5,33.34 45.72,35.56 IC6.27 58.74,35.56 60.01,36.83 63.5,36.83 64.77,35.56 IC8.27

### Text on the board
Bottom: WS1112 | Matthias Larisch | Nils Heitmann | DOA1 | HSE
